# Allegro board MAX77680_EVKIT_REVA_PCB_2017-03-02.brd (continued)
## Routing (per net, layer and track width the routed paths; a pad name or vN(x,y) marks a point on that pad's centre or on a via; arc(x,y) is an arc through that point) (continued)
UNNAMED_4_LED_I189_B: length 2.6
  TOP w0.381: v1(35.01,81.25) 35.68,81.25 35.69,81.25 D103.K
  BOTTOM w0.381: R161.1 v1(35.01,81.25)
UNNAMED_4_MAX8512_I5_FB: length 2.4
  BOTTOM w0.381: R160.2 R1.1 8.78,89.14 U103.4
UNNAMED_6_24AA02_I452_SCL: length 2.5
  BOTTOM w0.381: R162.2 51.47,79.33 51.43,79.3 U108.1
UNNAMED_6_24AA02_I452_SDA: length 2.4
  BOTTOM w0.381: R164.1 52.13,77.39 52.11,77.4 U108.3
UNNAMED_6_24AA02_I452_VCC: length 2.9
  BOTTOM w0.381: U108.4 47.44,77.37 C14.2 45.52,77.37 45.49,77.4 R163.1
UNNAMED_6_24AA02_I452_WP: length 2
  BOTTOM w0.254: U108.5 47.25,79.3 46.47,80.08 R165.1
UNNAMED_6_CAPNP_I21_1: length 29.5
  INTERNAL3 w0.254: v1(69.82,52.53) 69.82,52.22 69.87,52.17 v1(69.87,44.63) ; v1(58.67,51.97) 58.67,48.66 58.49,48.48 v1(58.49,47.78)
  BOTTOM w0.254: v1(69.82,52.53) 65.81,52.53 65.25,51.97 v1(58.67,51.97) ; C203.1 69.87,45.75 v1(69.87,44.63) ; C203.1 69.86,45.78 69.62,46.02 69.42,46.02 69.16,46.27 69.16,46.56 68.81,46.91 U200.7 ; C203.1 69.83,45.79 69.83,45.89 70.7,45.89 R205.1 ; v1(58.49,47.78) 58.92,47.78 R202.2
UNNAMED_6_CAPNP_I271_2: length 16
  BOTTOM w0.127: U201.5 68.47,37.64 69.69,38.86 73.2,38.86 77.16,42.82 R229.1
  BOTTOM w0.152: R295.1 70.41,38.88 70.43,38.86
  BOTTOM w0.254: U201.5 67.36,38.24 67.37,38.25 C208.2 67.37,40.27 R226.2
UNNAMED_6_CAPNP_I277_1: length 22.8
  INTERNAL3 w0.254: v1(69.34,33.35) v1(69.34,34.85) ; v1(58.42,37.21) 58.42,34.65 v1(57.1,33.32)
  BOTTOM w0.254: C209.1 69.35,35.64 R228.1 ; v1(69.34,34.85) R228.1 ; R228.1 69.25,35.62 68.54,36.34 U201.7 ; v1(69.34,33.35) 61.57,33.35 61.54,33.32 v1(57.1,33.32) ; v1(58.42,37.21) 58.95,37.21 R223.2
UNNAMED_6_CAPNP_I277_2: length 15.2
  BOTTOM w0.127: 68.55,37 68.55,37.33 69.75,38.52 73.39,38.52 76.89,42.03 R230.1
  BOTTOM w0.152: R296.2 70.43,38.5 70.41,38.52
  BOTTOM w0.254: 68.54,36.99 69.2,36.99 R228.2 70.34,36.84 C209.2 ; 68.54,36.99 U201.6 ; 68.54,36.99 68.55,37
UNNAMED_6_CAPNP_I289_2: length 3.2
  BOTTOM w0.254: R224.2 60.11,37.91 60.42,37.6 60.42,37.57 60.75,37.24 C248.2 60.84,37.16 61.02,36.99 U201.3
UNNAMED_6_CAPNP_I307_2: length 15.9
  BOTTOM w0.127: 67.99,29.56 68.96,29.56 70.21,30.81 73.14,30.81 77.23,34.9 77.58,34.9 78.01,35.33 R242.1
  BOTTOM w0.152: 70.56,30.81 70.57,30.82 R297.1
  BOTTOM w0.254: R240.2 67.4,30.89 C214.2 67.39,30.2 67.42,30.17 U202.5 67.99,29.56
UNNAMED_6_CAPNP_I311_1: length 24.1
  INTERNAL3 w0.254: v1(70.26,24.71) v1(70.26,26.92) ; v1(58.93,29.71) v1(58.93,24.71)
  BOTTOM w0.254: C213.1 70.26,27.57 v1(70.26,26.92) ; C213.1 69.42,27.74 69.34,27.74 68.81,28.26 U202.7 ; C213.1 71.16,27.74 R239.1 ; R236.2 58.89,29.67 v1(58.93,29.71) ; v1(58.93,24.71) v1(70.26,24.71)
UNNAMED_6_CAPNP_I311_2: length 15.9
  BOTTOM w0.127: R243.1 77.34,34.5 73.27,30.43 70.31,30.43 68.79,28.91
  BOTTOM w0.152: R298.2 70.55,30.42 70.56,30.43
  BOTTOM w0.254: 70.12,28.91 70.13,28.91 70.17,28.94 R239.2 ; 70.12,28.91 70.12,28.92 C213.2 ; 70.12,28.91 U202.6
UNNAMED_6_CAPNP_I323_2: length 3.3
  BOTTOM w0.254: U202.3 61.81,28.91 61.56,29.16 C250.2 60.81,29.16 60.55,29.41 60.55,29.41 60.47,29.49 60.47,29.49 60.27,29.69 59.85,29.69 R237.2
UNNAMED_6_CAPNP_I359_2: length 3.2
  BOTTOM w0.254: U200.3 61.21,47.56 C200.2 60.75,47.93 60.23,48.45 R203.2
UNNAMED_6_EKCAPNP_I10_1: length 3.8
  BOTTOM w0.254: R202.1 59.88,47.72 C201.1 59.89,46.8 60.81,46.8 60.92,46.91 U200.2
UNNAMED_6_EKCAPNP_I10_2: length 1.2
  BOTTOM w0.254: C201.2 58.98,45.68 R201.1
UNNAMED_6_EKCAPNP_I203_2: length 2
  BOTTOM w0.254: U205.1 65.77,73.55 65.83,73.48 C223.2
UNNAMED_6_EKCAPNP_I237_2: length 1.1
  TOP w0.381: v1(86.54,48.56) 86.43,48.67 C239.2
  BOTTOM w0.381: Q200.8 87,48.56 v1(86.54,48.56)
UNNAMED_6_EKCAPNP_I261_2: length 1.3
  TOP w0.254: C240.2 v1(86.71,40.93)
  BOTTOM w0.381: Q201.8 87.25,40.93 v1(86.71,40.93)
UNNAMED_6_EKCAPNP_I287_1: length 4
  BOTTOM w0.254: R223.1 59.9,37.16 C206.1 59.9,36.08 60.83,36.08 61.09,36.34 U201.2
UNNAMED_6_EKCAPNP_I287_2: length 1.2
  BOTTOM w0.254: R222.1 59.01,36.07 C206.2
UNNAMED_6_EKCAPNP_I298_2: length 1.5
  TOP w0.254: v1(86.56,33.5) 86.66,33.5
  TOP w0.381: C241.2 86.61,33.56 86.66,33.5
  BOTTOM w0.254: v1(86.56,33.5) 87.14,33.5
  BOTTOM w0.381: 87.14,33.5 Q202.8
UNNAMED_6_EKCAPNP_I321_1: length 4.1
  BOTTOM w0.254: R236.1 59.79,29 C211.1 60.37,27.97 60.67,28.26 U202.2
UNNAMED_6_EKCAPNP_I321_2: length 1.1
  BOTTOM w0.254: R235.1 58.89,26.9 C211.2
UNNAMED_6_EKRESSMD_I42_1: length 15.5
  BOTTOM w0.127: U200.5 68.52,48.21 68.98,48.68 70.03,48.68 ; 70.03,48.68 76.06,48.68 77.31,49.93 R207.1 ; 70.03,48.68 70.02,48.68 R293.1
  BOTTOM w0.254: 67.44,50.85 67.46,50.84 67.46,49.1 67.4,49.05 U200.5 ; 67.44,50.85 C204.2 ; 67.44,50.85 R206.2
UNNAMED_6_EKRESSMD_I42_2: length 12
  BOTTOM w0.127: R211.1 85.35,51.03 85.27,50.95 84.47,50.95 82.92,49.4 79.78,49.4 79.25,49.93 R207.2
  BOTTOM w0.889: R211.1 82.84,51.59 81.95,50.7 VIL_SBB0.1
UNNAMED_6_EKRESSMD_I43_1: length 14.4
  BOTTOM w0.127: 69.98,48.36 69.06,48.36 68.63,47.93 68.63,47.59 68.66,47.56 ; 69.98,48.36 76.23,48.36 77,49.14 R208.1 ; 69.98,48.36 69.98,48.36 R294.2
  BOTTOM w0.254: R205.2 70.7,47.11 69.99,47.11 C203.2 69.5,46.98 68.94,47.55 68.67,47.55 68.66,47.56 U200.6
UNNAMED_6_EKRESSMD_I99_1: length 4.2
  BOTTOM w0.254: U200.1 61.49,46.26 61.23,45.99 61.23,45.91 60.9,45.58 60.81,45.58 ; 60.81,45.58 60.69,45.46 R204.1 ; 60.81,45.58 60.72,45.67 R201.2
UNNAMED_6_EKRESSMD_I99_2: length 46.8
  INTERNAL3 w0.254: v1(59.21,55.68) 59.21,45.24 59.17,45.21 v1(59.17,44.6)
  BOTTOM w0.254: J200.1 92.46,54.51 92.45,54.52 89.88,54.52 88.56,55.83 75.98,55.83 75.82,55.68 v1(59.21,55.68) ; R204.2 v1(59.17,44.6)
UNNAMED_6_EKRESSMD_I207_1: length 1.6
  BOTTOM w0.254: R214.1 65.77,82.56 U205.14
UNNAMED_6_EKRESSMD_I222_2: length 1.6
  BOTTOM w0.254: R283.2 64.48,80.96 U205.12
UNNAMED_6_EKRESSMD_I273_2: length 11.7
  BOTTOM w0.127: R229.2 78.76,42.83 79.08,42.83 80.35,41.55 83.36,41.55 84.49,42.68 85.25,42.68 85.34,42.76 R233.1
  BOTTOM w0.889: VIL_SBB1.1 83.52,42.81 84.04,43.33 R233.1
UNNAMED_6_EKRESSMD_I278_1: length 4.4
  BOTTOM w0.254: U201.1 62.66,35.08 62.44,34.86 60.83,34.86 60.79,34.91 R222.2 59.89,34.89 R225.1
UNNAMED_6_EKRESSMD_I278_2: length 69.1
  INTERNAL3 w0.254: v1(55.02,34.01) 55.02,33.4 54.89,33.27 v1(54.89,24.06) ; v1(92.1,24.06) 92.56,24.52 92.56,39.88 92.7,40.02 92.7,40.14 J202.1
  BOTTOM w0.254: R225.2 v1(55.02,34.01) ; v1(92.1,24.06) v1(54.89,24.06)
UNNAMED_6_EKRESSMD_I306_2: length 12.1
  BOTTOM w0.127: R242.2 79.43,35.38 80.47,34.34 83.55,34.34 84.95,35.74 84.96,35.74 84.97,35.75 85.51,35.75 85.6,35.84 85.6,36.38 R245.1
  BOTTOM w0.889: R245.1 83.27,36.41 VIL_SBB2.1
UNNAMED_6_EKRESSMD_I313_1: length 4.1
  BOTTOM w0.254: U202.1 61.32,27.61 60.55,26.84 R235.2 59.78,26.77 R238.1
UNNAMED_6_EKRESSMD_I313_2: length 39.2
  BOTTOM w0.254: J204.1 93.94,28.19 93.98,28.14 93.98,26.13 93.19,25.33 59.19,25.33 58.88,25.65 R238.2
UNNAMED_6_EKRESSMD_I450_2: length 1.5
  BOTTOM w0.203: U205.10 63.17,82.35 R305.2
UNNAMED_6_EKRESSMD_I451_2: length 2.7
  BOTTOM w0.203: R306.2 63.08,83.25 63.82,82.51 U205.11
UNNAMED_6_HEADER2P_I444_2: length 5.3
  BOTTOM w0.254: Q201.4 89.81,43.97 90.24,44.4 90.53,44.4 90.53,44.39 R231.2 92.19,44.39 92.73,43.85 93.99,43.85 93.96,43.82 J202.2
UNNAMED_6_HEADER2P_I446_2: length 9.6
  INTERNAL3 w0.254: J204.2 93.94,31.91 93.98,31.87
  INTERNAL3 w0.381: 93.98,31.87 93.98,35.93 93.92,35.98 v1(93.92,36.66)
  BOTTOM w0.508: Q202.4 92.03,36.76 92.14,36.66 R244.2 v1(93.92,36.66)
UNNAMED_6_MAX5815_I205_OUTD: length 2.3
  BOTTOM w0.254: U205.6 62.52,73.83 62.31,73.61 61.98,73.61 TP1.1
UNNAMED_6_RESSMD_I28_2: length 5.4
  BOTTOM w0.254: J200.2 94.05,51.97 94.06,51.98 91.59,51.98 91.52,51.9 R210.2 90.08,51.9 89.97,51.8 Q200.4
VIO: length 159.8
  TOP w0.254: v1(10.06,27.92) 10.03,27.95 R10.1 ; R17.2 23.3,44.42 20.68,47.04 v1(10.08,47.04) ; v1(34.79,87.72) v1(32.78,87.72) v1(30.47,87.72) ; v1(10.08,41.94) 9.74,42.28 J2.1
  TOP w0.381: v1(34.79,87.72) 35.46,87.72 35.5,87.76 v1(38.18,87.76) ; v1(38.18,83.92) 20.17,83.92 18.95,82.7 v1(17.14,82.7) ; 18.11,47.04 18.08,47.07 v1(17.88,47.07)
  TOP w0.508: v1(38.18,87.76) v1(43.76,87.76)
  INTERNAL3 w0.152: 10.06,27.91 v1(10.06,27.92)
  INTERNAL3 w0.254: 10.06,27.91 10.06,41.66 10.08,41.68 v1(10.08,41.94) v1(10.08,47.04) ; v1(10.06,27.92) v1(10.06,14.48)
  INTERNAL3 w0.381: v1(38.18,87.76) v1(38.18,83.92) ; v1(17.88,47.07) 17.88,56.74 17.14,57.48 v1(17.14,82.7)
  INTERNAL3 w0.508: J101.2 43.79,92.67 43.76,92.65 v1(43.76,87.76)
  BOTTOM w0.254: C120.2 29.08,86.28 29.86,85.5 U107.12 30.23,86.88 30.47,87.11 v1(30.47,87.72) 30.47,88.34 R108.1 ; R107.1 33.04,87.98 v1(32.78,87.72) ; R14.2 34.79,88.35 v1(34.79,87.72)
  BOTTOM w0.381: v1(38.18,83.92) 37.28,83.92 37.27,83.91 R143.1
  BOTTOM w0.508: v1(10.06,14.48) 22.68,14.48 22.7,14.45 J4.1
VSYS: length 92.5
  TOP w0.152: U1.E2 46.49,40.34 ; U1.E3 46.89,40.34 ; 47.15,40.34 47.29,40.48 U1.E4
  TOP w0.254: R2.2 v1(7.12,58.13) ; 47.15,40.17 47.15,40.34
  TOP w0.508: C30.1 v1(43.34,18.12) ; v1(7.12,58.13) 6.26,58.13 2.97,61.42 2.97,63.39 2.32,64.04 SW2.1
  INTERNAL3 w0.508: v1(7.12,58.13) 7.12,57.4 7.1,57.38 v1(7.1,19.94)
  BOTTOM w0.508: VSYS.1 38.27,17.83 10.87,17.83 8.76,19.94 v1(7.1,19.94)
  vias: v1(41.07,18.08) v1(41.1,17.14) v1(42.27,18.11) v1(42.27,17.17) v1(43.33,17.14) v1(43.33,15.72) v1(43.33,14.1) v1(43.28,13.03) v1(44.35,13) v1(44.4,17.12) v1(44.4,15.7) v1(44.4,14.07) v1(45.47,39.85) v1(45.47,39.19) v1(46.08,39.85) v1(46.08,39.17)
VUSB: length 168.8
  TOP w0.381: v1(46.53,85.47) 45.8,86.21 20.38,86.21 v1(18.59,84.41) v1(10.14,84.41) ; v1(48.55,70.54) v1(66.73,70.54)
  INTERNAL3 w0.381: v1(48.55,70.54) v1(48.55,82.58) v1(48.55,94.01) ; v1(10.14,77.91) v1(10.14,84.41) ; v1(66.85,44.6) 66.84,44.6 66.73,44.71 v1(66.73,70.54)
  INTERNAL3 w0.508: v1(66.84,26.44) v1(66.84,34.57) 66.84,44.6
  BOTTOM w0.254: FB100.2 9.88,76.86 10.3,76.44 C108.2 15.84,76.14 U101.19 ; C202.1 67.4,45.23 U200.8 ; U202.8 67.4,27.61 67.4,26.48 C212.1 v1(66.84,26.44) ; U201.8 67.36,34.58 C207.1 v1(66.84,34.57)
  BOTTOM w0.381: U104.3 16.49,86.39 16.84,86.74 17.59,86.74 17.86,86.47 17.86,85.6 U104.1 17.75,85.49 C112.2 18.03,84.41 v1(18.59,84.41) ; v1(48.55,94.01) 51.53,94.01 51.56,94.03 J100.1 ; v1(46.53,85.47) 46.72,85.47 46.83,85.58 47.24,85.58 47.24,85.49 ; C202.1 66.85,44.66 v1(66.85,44.6) ; U102.3 47.24,85.49 ; 47.24,85.49 47.51,85.76 48.38,85.76 48.65,85.49 48.65,84.7 U102.1 48.54,83.26 C118.2 v1(48.55,82.58) ; R115.1 v1(10.14,77.91) ; R115.1 C154.2 ; R115.1 9.02,77.88 FB100.2 ; v1(10.14,84.41) 10.14,85.25 C110.2 10.13,86.68 U103.1 10.12,87.48 9.74,87.86 9.14,87.86 8.82,87.53 U103.3

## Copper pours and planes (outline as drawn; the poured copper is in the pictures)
GROUND on TOP: 0.99,95.55 0.99,11.02 95.94,11.02 95.94,95.55 ; 6 cut-outs
GROUND on BOTTOM: 1.4,94.87 1.55,10.74 95.66,10.87 95.63,96.01 3.56,96.01 ; 22 cut-outs
GROUND on INTERNAL2: 1.3,95.28 1.3,11.23 95.4,11.23 95.4,95.28 ; 1 cut-out
LXA on TOP: 46,36.07 46,38.48 47.27,38.48 47.27,36.07
LXB on TOP: 47.88,36.07 47.88,38.48 49.15,38.48 49.15,36.07
SBB0 on TOP: 48.39,41.43 48.39,41.55 48.64,41.8 48.64,44.22 52.07,47.65 86.66,47.65 86.66,45.01 59.33,45.01 58.67,44.98 54.23,44.98 52.45,43.21 50.55,43.21 48.77,41.43
SBB1 on TOP: 52.96,40.67 53.34,40.28 54.99,40.28 57.53,37.74 86.66,37.69 86.66,39.93 86.46,40.13 58.55,40.16 56.77,41.94 51.18,41.94 50.67,41.43 50.67,40.92 50.93,40.67
SBB2 on TOP: 50.8,39.78 60.96,29.62 86.56,29.57 86.77,29.77 86.77,32.61 61.26,32.61 53.98,40.03 53.09,40.03 52.7,40.41 50.8,40.41
UNNAMED_6_EKCAPNP_I237_2 on BOTTOM: 87,45.09 91.77,45.06 91.77,50.85 87,50.88
UNNAMED_6_EKCAPNP_I261_2 on BOTTOM: 87.09,41.27 87.09,37.8 91.8,37.77 91.8,41.27 90.55,42.49 90.53,43.08 87.1,43.08
UNNAMED_6_EKCAPNP_I298_2 on BOTTOM: 87.12,35.92 87.11,30.45 91.69,30.45 91.72,35.92
UNNAMED_6_EKRESSMD_I42_2 on BOTTOM: 88.65,51.44 86.61,51.44 86.23,51.05 84.84,51.05 84.84,52.2 85.34,52.7 88.65,52.7
UNNAMED_6_EKRESSMD_I273_2 on BOTTOM: 88.65,44.45 88.65,43.56 86.74,43.56 86.08,42.89 84.96,42.89 84.96,44.07 85.34,44.45
UNNAMED_6_EKRESSMD_I306_2 on BOTTOM: 88.77,36.32 86.87,36.32 86.5,35.96 85.21,35.95 85.22,37.21 88.77,37.21
VSYS on TOP: 46.35,40.51 47.24,40.51 47.24,38.86 45.21,38.86 45.21,40.11 45.95,40.11
VSYS on TOP: 39.62,18.97 39.62,12.75 44.63,12.75 44.63,18.97
VSYS on INTERNAL3: 35.56,60.96 35.56,12.7 60.96,12.7 60.96,60.96 ; 1 cut-out

Small or netless copper shapes (teardrops, artwork), in the pictures only: 2 on TOP, 2 on INTERNAL2

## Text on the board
Ref Des/Silkscreen Top: EN_EXT | SCL | SDA | GND | nIRQ | nRST | VIO | nEN | PWRHLD | SW2 | GPIO | SW1 | RX | TX | INTERRUPT | PENDING | 3.3V_OK | 3.3V | 1.8V | VUSB | +3.3V | SCL1 | SDA1 | ENEXT | LB 02/17 | www.maximintegrated.com | 1-408-601-1000 | MAX77680 EV KIT | REVA
FAB_NOTES: NOTES: | FINISH: | TESTING: | MISCELLANEOUS: | TOOLING: | 15.  CHECK ALL THAT APPLY | 16.  VENDOR LOGO & DATE CODE REQUIRED IN INK ON BOTTOM SIDE ONLY. DATE CODE FORMAT MUST BE YYWW ONLY | 17.  FINAL ELECTRICAL TEST TO BE PERFORMED USING PROVIDED IPC-D-356A NETLIST OR ODB++ FORMAT FILE. | 18.  A TIME DOMAIN REFLECTOMETER REPORT FOR EACH IMPEDANCE CONTROLLED LAYER AND A CERTIFICATE | 24.  THIEVING: | 23.  FINISHED SURFACE CONTACTS AND FILLED VIAS TO BE FREE OF ANY PITS. SCRATCHES PROBE MARKS | 19.  FOR BLIND AND BURIED VIA INFORMATION REFER TO DRILL CHART. | 21.  ALL MICRO-VIAS LESS THAN 0.006 INCHES FHS WILL BE PLATED SHUT WITH COPPER, UNLESS OTHERWISE SPECIFIED. | 22.  FOR VIA SIZES XX.XX INCH USE NON CONDUCTIVE VIA FILL AND CAP | 13.  DRILL SIZES ARE FINISHED HOLE SIZES. ALL HOLES SHALL BE LOCATED WITHIN .005 DTP. | 14.  CHECK ALL THAT APPLY | 25.  PEMNUT | 9.  ALL TRACES FILLETED OPTION TO ENHANCE RELIABILITY AT PAD JUNCTIONS | 10.  LAYER TO LAYER REGISTRATIONS SHALL BE WITHIN .003 INCHES. | MATERIAL: | 11.  FINISHED COPPER WEIGHT/THICKNESS: | 12.  CHECK ALL THAT APPLY | 8.  IF STATED IN THE LAMINATION DIAGRAM, THE DIELECTRIC THICKNESS OF ANY | 1.  DIMENSIONS ARE IN INCHES (EXCEPT WHERE NOTED). | 3.  THE PCB SHALL BE FABRICATED TO IPC-6012, TYPE X, CLASS 2. | 4.  BOARD MATERIAL & CONSTRUCTION SHALL MEET THE REQUIREMENTS OF UL796 | 5.  OVERALL BOARD THICKNESS REFER TO LAMINATION DIAGRAM. TOLERANCE APPLIES | 6.  BOW & TWIST NOT TO EXCEED 0.0075 IN. (0.75%) PER LINEAR INCH. | 7.  PHOTO ETCH CIRCUITRY PER ENCLOSED GERBER RS274X OR ODB++ FORMAT FILE. | 2.  BOARD MATERIAL: | ( )  APPLY SILKSCREEN TO TOP SIDE USING A NON-CONDUCTIVE, WHITE EPOXY | ( )  OTHER ________________________ | (x)  APPLY SILKSCREEN TO BOTH SIDES USING A NON-CONDUCTIVE, WHITE EPOXY | (x)  GREEN SOLDERMASK OVER BARE COPPER/BARE GOLD (BOTH SIDES) WITH LIQUID PHOTO IMAGEABLE INK (LPI) | ( )  GREEN TAIYO PSR-4000 | (X)  REFER TO LAMINATION DIAGRAM FOR FINISHED COPPER WEIGHT/THICKNESS REQUIREMENTS. | ( )  FINGERS TO BE GOLD PLATED. | ( )  FINISH CONDUCTOR SURFACES: IMMERSION GOLD, 2-5 MICRO INCHES OVER | (X)  SUPPLIER MAY ADD THIEVING TO COMPENSATE FOR LOW COPPER DENSITY AREAS ON THIS DESIGN. | ( )  SUPPLIER MAY NOT ADD THIEVING TO COMPENSATE FOR LOW COPPER DENSITY AREAS ON THIS DESIGN. | ( )  NON-CONDUCTIVE EPOXY. FILL AND CAP ALL 0.XXXX INCH DRILLED VIAS. | ( )  SILVER. FILL AND CAP ALL 0.XXXX INCH DRILLED VIAS. | ( )  ELECTODEPOSITED HARD GOLD PLATE, TYPE 1 (99.7% MIN GOLD), GRADE C | (X) LEAD FREE AND RoHS COMPLIANT OR EQUIVALENT LEAD FREE PLATING | (REQUIRED UNLESS OTHERWISE SPECIFIED IN QUOTE) | THE PCB SHALL HAVE A VERIFICATION STAMP. | OF COMPLIANCE SHALL BE PROVIDED BY VENDOR AT TIME OF SHIPMENT. | ( )  PEMNUT TO BE INSTALLED BY SUPPLIER | ( )  PEMNUT NOT TO BE INSTALLED BY SUPPLIER | OR OTHER DEFORMITIES THAT COULD EFFECT THE APPERANCE AND PERFORMACE OF THE CONTACT | SURFACE. CONTACTS ARE TO BE AS FLAT AS POSSIBLE. NOT TO EXCEED +/- 0.001" OF FLATNESS. | (x)  FINISH CONDUCTOR SURFACES: IMMERSION GOLD, 3-8 MICRO INCHES OVER | ( )  FILLETED | (X)  NOT FILLETED | SO AS TO HINDER PROPER SOLDER WICKING. | (X)  ISOLA 370HR OR EQUIVALENT | ( )  NELCO-4000-13 | ( )  MEGTRON 6 | ( )  ROGERS 4350B | ( )  ROGERS 4003C | MINIMUM BARREL PLATING OF .001 IN. PLATED HOLES SHALL NOT BE ROUGH OR IRREGULAR | ( )  ISOLA-FR408HR OR EQUIVALENT | CONTROLLED IMPEDANCE LAYER IS FOR REFERENCE ONLY. FINAL ACCEPTANCE | SHALL BE DETERMINED BY THESE LAYERS HAVING A CHARACTERISTIC | IMPEDANCE OF +/-10% OHMS AS STATED IN THE LAMINATION DIAGRAM. THE | VENDOR CAN MAKE ADJUSTMENTS AS LONG AS THE STATED IMPEDANCE AND | OVERALL BOARD THICKNESS IS MAINTAINED. ANY ADJUSTMENT MADE TO TRACE | WIDTH OR SPACING MUST HAVE PRIOR WRITTEN APPROVAL FROM MAXIM. | WHERE SPACING PERMITS. | LEGEND TO LEGEND +/- 0.007 INCHES | WORKMANSHIP SHALL CONFORM TO IPC-A-600, CLASS 2, CURRENT REVISIONS. | WITH FLAMMABILITY RATING OF 94V-O. | AFTER ALL LAMINATION AND PLATING PROCESSES. IT IS TO BE MEASURED FROM | TOP PCB METAL TO BOTTOM PCB METAL UNLESS OTHERWISE SPECIFIED. | BOW & TWIST SHOULD BE MEASURED PER IPC-TM-650, METHOD 2.4.22. | DRILL LOCATION AND SIZE CONTROLLED BY EXCELLON CNC DRILL FILE. | UNLESS OTHERWISE SPECIFIED | BASED INK PER ARTWORK. | PER ARTWORK. | THE STARTING COPPER WEIGHT/THICKNESS CAN VARY AS LONG AS THE FINISHED COPPER | WEIGHT/THICKNESS IS NOT LESS THAN THE SPECIFIED VALUE. UNLESS OTHERWISE SPECIFIED. | (KNOOP HARDNESS 130-200), CLASS 1 (50-100 MICRO INCHES THICK) IN ACCORDANCE WITH MIL-G-45204C. | GENERAL SURFACING REQUIREMENTS MUST MEET ANSI/IPC-A-600(CURRENT REV) SECTION 4.0, | CLASS 3 (50-100 MICROINCHES THICK) OVER ELECTRODEPOSITED NICKEL PLATE | IN ACCORDANCE WITH ANSI/IPC-A-600D, SECTION 4.0, CLASS 3 (200-600 MICROINCHES THICK). | 118-236 MICRO INCHES MINIMUM OF ELECTROLESS NICKEL. | 100 MICRO INCHES MINIMUM OF ELECTROLESS NICKEL. | (USE CHECKED ITEMS FOR MATERIAL) | (USE CHECKED ITEMS FOR PLATING) | (USE CHECKED ITEMS FOR TOOLING) | UNLESS OTHERWISE SPECIFIED: | NOT TO SCALE | TEMPLATE REV 1.7 | TOLERANCES UNLESS OTHERWISE SPECIFIED | +/- | FRACTIONS | SEE NOTES | .XXX +/- .005 | .XX +/- .01 | DECIMALS | ANGLES | THE INFORMATION CONTAINED IN THIS DOCUMENT | IS PROPRIETARY TO MAXIM. THE INFORMATION IN | THIS DOCUMENT IS NOT TO BE SHOWN, REPRODUCED, | OR DISCLOSED TO ANYONE OUTSIDE OF MAXIM | WITHOUT PRIOR WRITTEN PERMISSION FROM MAXIM. | DRAWN BY: | CHECKED BY: CHAD OLSON | APPR. BY: | LAKSHMI BHUJ | DATE: | 2/22/2017 | SIZE | E | DRAWING NO. | SHEET 1 OF 1 | REV | A | DESCRIPTION | REVISIONS | APPROVED | DATE | TITLE: | RELEASE | MAX77680 EVALUATION BOARD | FABRICATION DWG. | XX-XXXXXX-XX
User.25: FIGURE | SIZE | 4.0 | 8.0 | 12.01 | 39.37 | 45.28 | 62.99 | 70.87 | 125.0 | 35.43 | 41.34x25.59 | 51.18x27.56 | TOLERANCE | +0.0/-4.0 | +3.0/-6.0 | +3.0/-3.0 | PLATED | NON-PLATED | ALL UNITS ARE IN MILS | QTY | 20 | 309 | 9 | 17 | 39 | 4 | 5 | 2 | NOTES | DRILL CHART: TOP to BOTTOM
